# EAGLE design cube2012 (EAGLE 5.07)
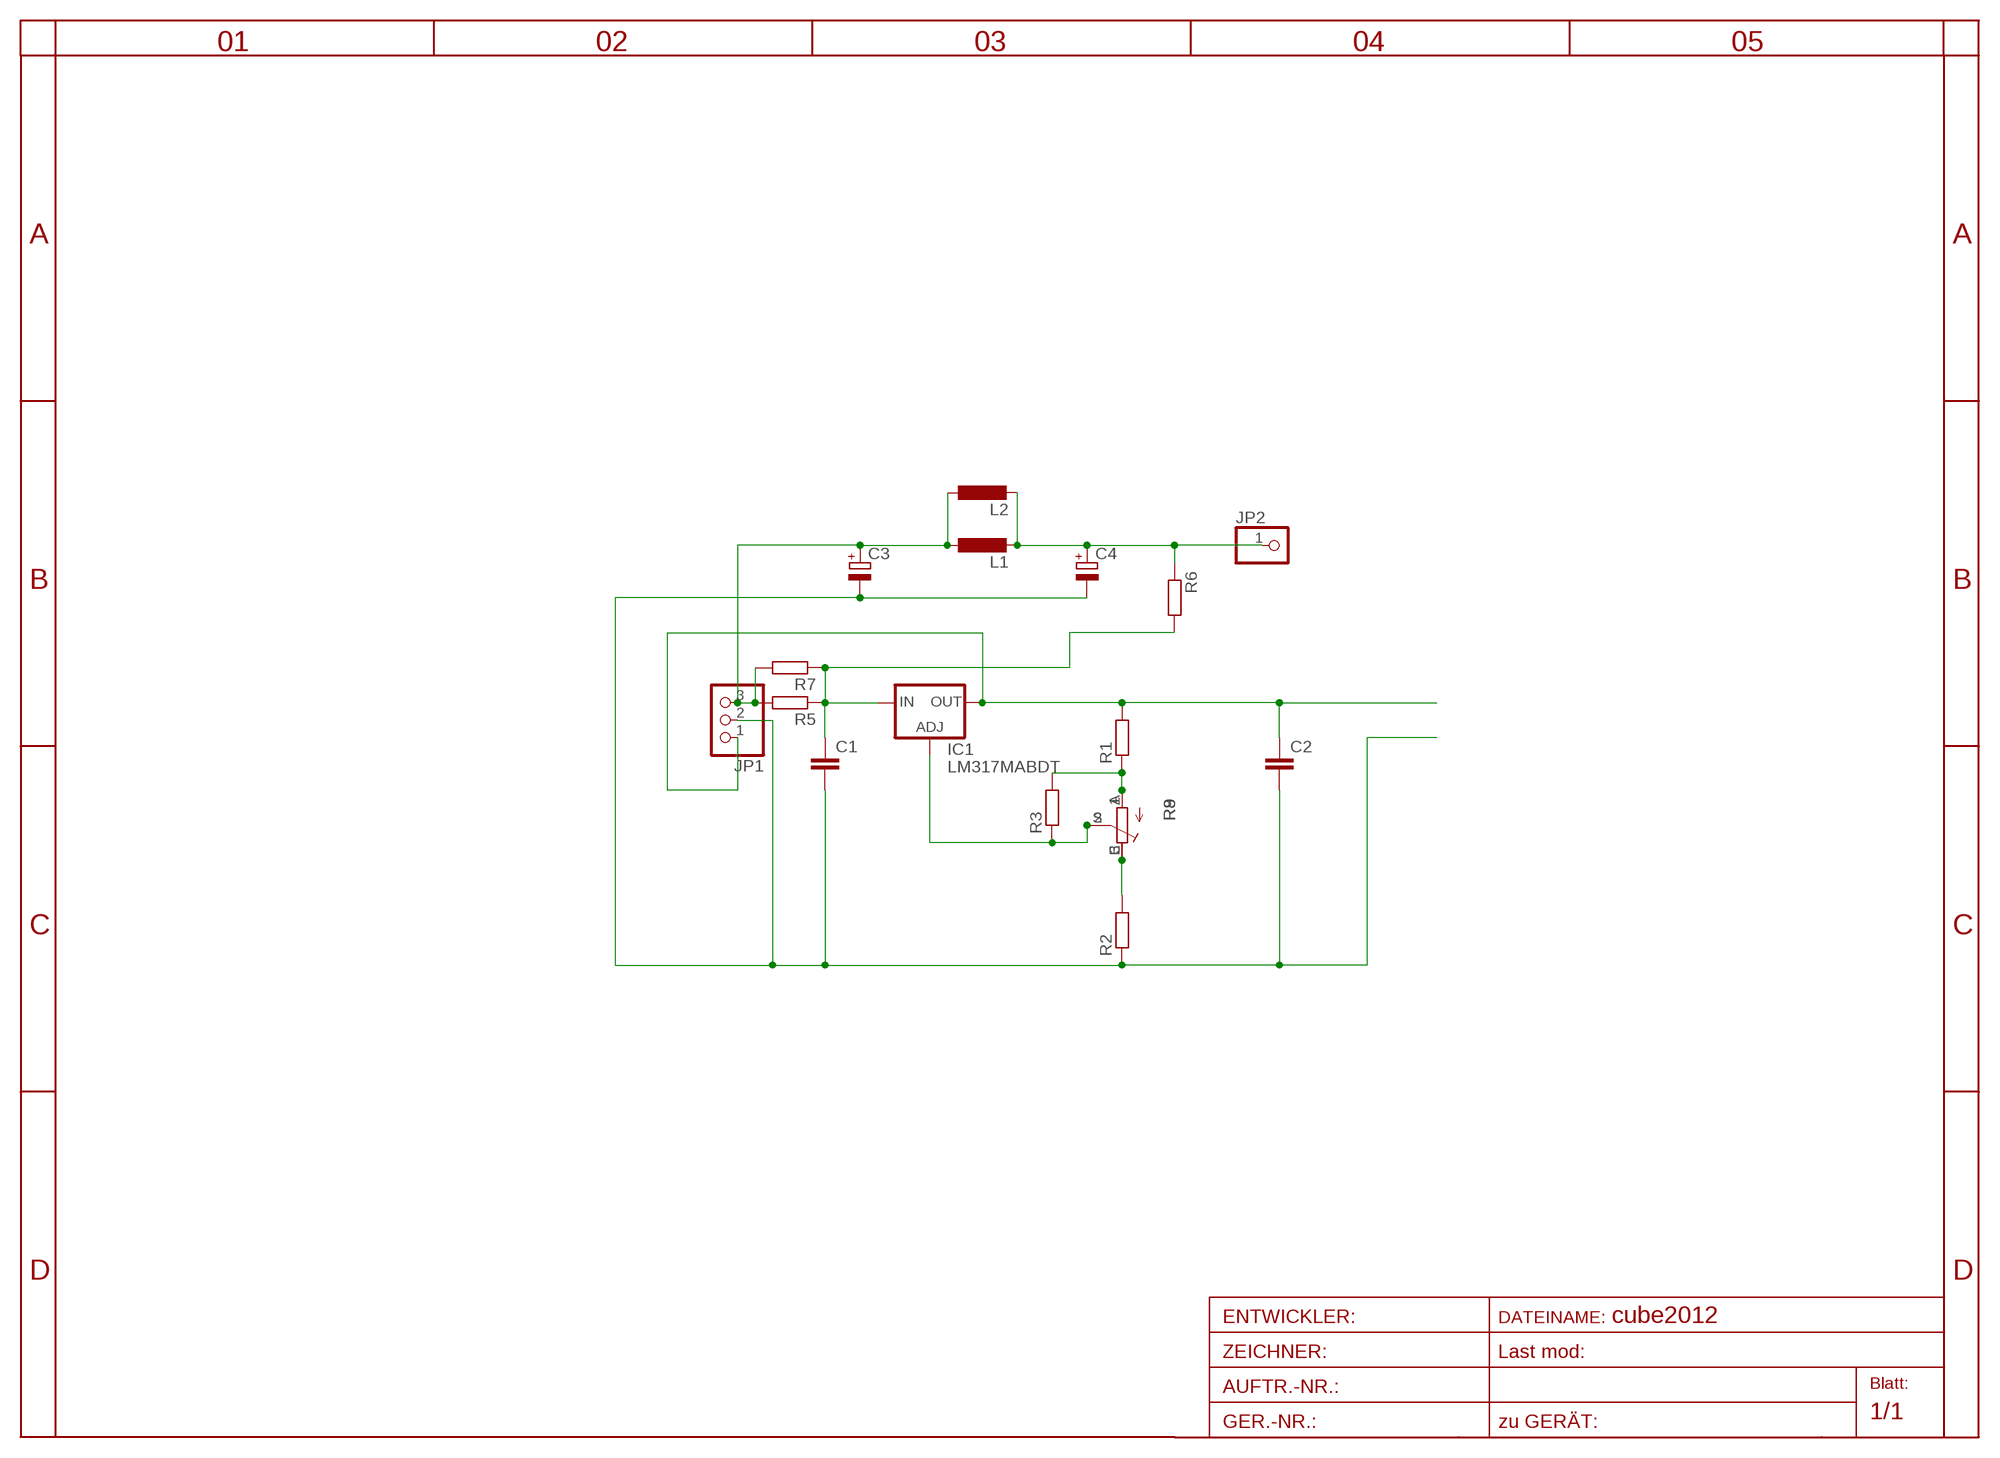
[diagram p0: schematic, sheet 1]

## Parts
C1  C-EUC1206  [C1206]
C2  C-EUC1206  [C1206]
C3  CPOL-EUE  [PANASONIC_E]
C4  CPOL-EUE  [PANASONIC_E]
IC1  LM317MABDT  [DPACK]
JP1  PINHD-1X3  [1X03]
JP2  PINHD-1X11X0.4  [1X01]
L1  L-EUPIS2816  [PIS2816]
L2  L-EUOPEN  [OPEN5]
R1  R-EU_R0805  [R0805]
R2  R-EU_R0805  [R0805]
R3  R-EU_R0805  [R0805]
R5  R-EU_R0805  [R0805]
R6  R-EU_R0805  [R0805]
R7  R-EU_R0805  [R0805]
R8  TRIM_EU-EVND_H  [EVND8AA]
R9  R-TRIMM3214W  [RTRIM3214W]

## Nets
GND: C1.2 C2.2 C3.- C4.- JP1.2 R2.1
IN: C1.1 IC1.3(IN) R5.1 R6.2 R7.1
N$1: C3.+ JP1.3 L1.1 L2.1 R5.2 R7.2
N$3: C4.+ JP2.1 L1.2 L2.2 R6.1
N$4: IC1.1(ADJ) R3.1 R8.S R9.2(S)
N$6: R2.2 R8.E R9.3(A)
N$7: R1.1 R3.2 R8.A R9.1(E)
OUT: C2.1 IC1.4(OUT) JP1.1 R1.2

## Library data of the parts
C1 C2 = rcl:C-EU: CAPACITOR, European symbol
C3 C4 = rcl:CPOL-EU: POLARIZED CAPACITOR, European symbol
IC1 = v-reg:LM317?*: 500 mA Adjustable Output Positive Voltage Regulator Source: http://www.onsemi.co.jp .. LM317M-D.PDF
JP1 = pinhead:PINHD-1X3: PIN HEADER
JP2 = pinhead:PINHD-1X1: PIN HEADER
L1 L2 = rcl:L-EU: INDUCTOR, European symbol
R1-R3 R5-R7 = rcl:R-EU_: RESISTOR, European symbol
R8 = pot:TRIM_EU-: POTENTIOMETER
R9 = rcl:R-TRIMM: Trimm resistor

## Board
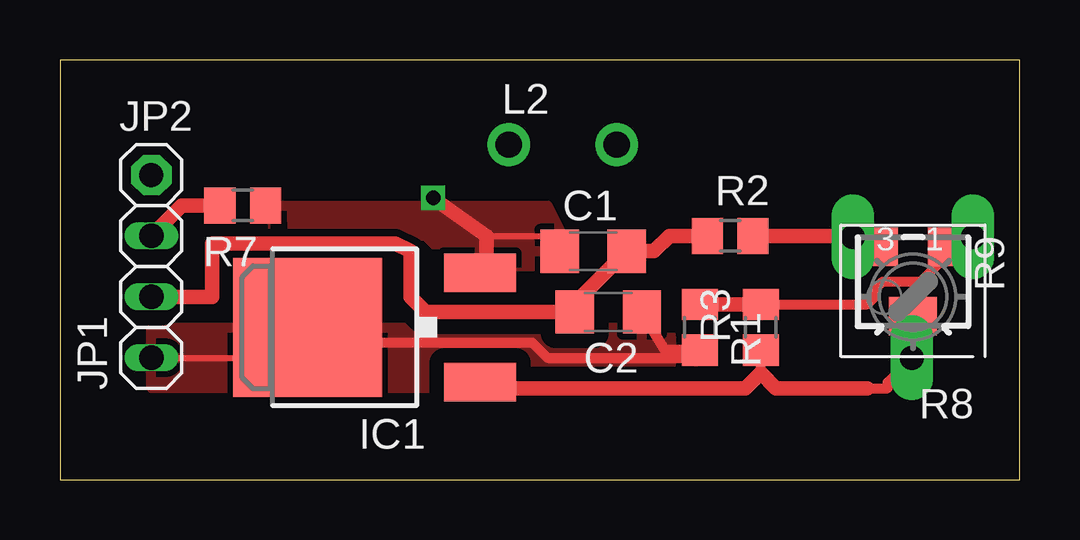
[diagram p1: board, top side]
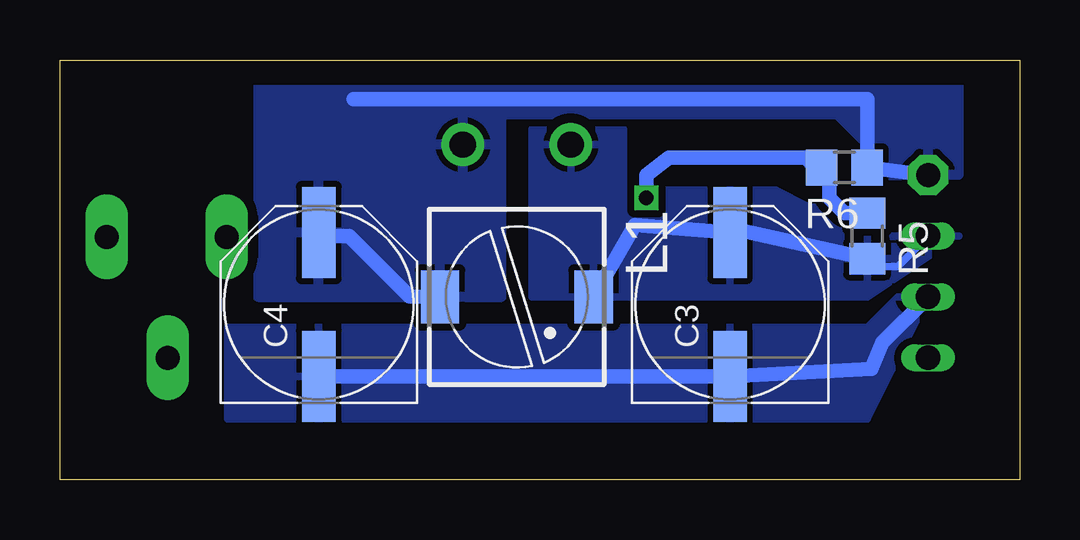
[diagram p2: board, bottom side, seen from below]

Size 40 x 17.5 mm. Coordinates in mm from the lower left corner, seen from the top.
Outline: 0,0 40,0 40,17.5 0,17.5 0,0
Copper layers (1*16): Top 0.035mm / dielectric 1.5mm / Bottom 0.035mm
Design rules "default": minimum track width 10mil, minimum drill 20mil, track to track 8mil, track to pad 8mil, pad to pad 8mil, via to via 8mil, smd to smd 8mil, copper to edge 40mil, drill to drill 8mil, minimum pad ring 1mil, minimum via ring 8mil, stop-mask expansion 4mil, vias tented up to drill 0mil, thermal gap 10mil

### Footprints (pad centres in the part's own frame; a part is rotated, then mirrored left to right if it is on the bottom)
C1206 = smd 1.6 x 1.8: 1 -1.4,0; 2 1.4,0
PANASONIC_E = smd 3.8 x 1.4: + 3,0; - -3,0
DPACK = smd 1.6 x 3: 1 -2.28,-4.8; 3 2.28,-4.8 | smd 5.8 x 6.2: 4 0,2.38
1X03 = drill 1.016 long: 1 -2.54,0; 2 0,0; 3 2.54,0
1X01 = drill 1 pad 1.676 octagon: 1 0,0
PIS2816 = smd 2.2 x 1.6: 1 0,3.2; 2 0,-3.2
OPEN5 = drill 1.1 pad 1.778 round: 1 -2.25,0; 2 2.25,0
R0805 = smd 1.3 x 1.5: 1 -0.95,0; 2 0.95,0
EVND8AA = drill 1 pad 1.778 long: A -2.5,-2.5; E 2.5,-2.5; S 0.04,2.54
RTRIM3214W = smd 1.3 x 1.6: 1 -1.275,-1.45; 3 1.275,-1.45 | smd 2 x 1.6: 2 0,1.45

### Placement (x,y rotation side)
C1  22.23,9.53 0 top
C2  22.86,6.99 180 top
C3  12.06,7.3 90 bottom
C4  29.21,7.3 90 bottom
IC1  12.7,6.35 90 top
JP1  3.81,7.62 90 top
JP2  3.81,12.7 0 top
L1  20.95,7.62 270 bottom
L2  20.95,13.97 0 top
R1  26.67,6.35 270 top
R2  27.94,10.16 0 top
R3  29.21,6.35 90 top
R5  6.35,10.16 270 bottom
R6  7.3,13.02 180 bottom
R7  7.62,11.43 180 top
R8  35.56,7.62 180 top
R9  35.56,8.26 180 top

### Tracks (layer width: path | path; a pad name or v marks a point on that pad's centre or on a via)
GND
  Top 0.406: C2.2 21.09,6.99
  Top 0.61: R2.1 25.4,10.16 24.77,9.53 C1.2 21.09,6.99 | JP1.2 6.35,7.62 6.35,9.85 13.97,9.85 14.61,9.53 14.61,7.62 15.24,6.99 C2.2
  Bottom 0.61: C4.- C3.- 6.17,4.62 5.71,5.71 JP1.2
  pour Bottom (isolate 0.305, rank 3): 3.81,7.62 5.08,7.62 6.35,6.35 33.02,6.35 33.02,2.54 6.35,2.54
IN  (via drill 0.6)
  Top 0.254: C1.1 20.32,10.16 17.78,10.16 IC1.3
  Top 0.61: v15.56,11.75 17.78,10.16 17.78,8.91 IC1.3
  Bottom 0.61: v15.56,11.75 15.56,12.7 14.61,13.43 8.89,13.43 8.57,13.02 R6.2 7.94,12.7 7.94,11.75 7.3,11.11 R5.1
  pour Top (isolate 0.305): 20.32,11.43 21.59,8.89 16.51,8.89 15.24,10.16 8.89,10.16 8.89,11.43
N$1
  Top 0.61: R7.2 5.08,11.43 JP1.3
  Bottom 0.305: JP1.3 5.08,8.89 6.03,8.89 R5.2
  Bottom 0.61: R5.2 12.06,10.48 C3.+ 16.02,10.62 L1.1
  pour Bottom (isolate 0.305, rank 2): 2.54,10.16 6.35,7.62 20.32,7.62 20.32,14.61 16.51,14.61 16.51,12.06 10.16,12.06 8.89,11.43
N$3
  Bottom 0.61: L1.2 25.43,7.64 27.94,10.16 28.75,10.16 C4.+ | 27.77,15.88 6.35,15.88 6.35,13.97 R6.1 JP2.1
  pour Bottom (isolate 0.406): 2.54,16.51 31.75,16.51 31.75,7.62 21.59,7.62 21.59,15.24 7.62,15.24 6.35,13.97 6.35,12.7 2.54,12.7
N$4
  Top 0.406: 18.41,3.81 17.78,3.79 IC1.1 | 29.21,4.45 R3.1 | 33.66,3.81 34.5,3.81 34.5,4.06 R8.S | R8.S 35.56,5.04 | R9.2 35.56,5.12 R8.S
  Top 0.61: 18.41,3.81 28.57,3.81 29.21,4.45 29.84,3.81 33.66,3.81
N$6
  Top 0.406: 33.02,10.16 R8.E 33.48,9.71 R9.3
  Top 0.61: R2.2 33.02,10.16
N$7
  Top 0.406: R3.2 33.66,7.3 33.97,7.62 33.97,7.94 34.29,8.26 35.88,8.26 36.84,9.21 R9.1 37.65,9.71 R8.A
  Top 0.61: R1.1 R3.2
OUT
  Top 0.254: JP1.1 10.16,5.08 10.16,7.62 IC1.4
  Top 0.406: C2.1 25.21,5.4 R1.2 26.35,5.08 20.32,5.08 19.68,5.71 13.34,5.71 12.7,6.35 IC1.4
  pour Top (isolate 0.61): 3.81,6.35 25.4,6.35 26.67,5.08 25.4,3.81 3.81,3.81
